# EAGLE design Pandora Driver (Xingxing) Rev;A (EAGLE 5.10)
MFG: AVX; PN: TCJR106M006R0500

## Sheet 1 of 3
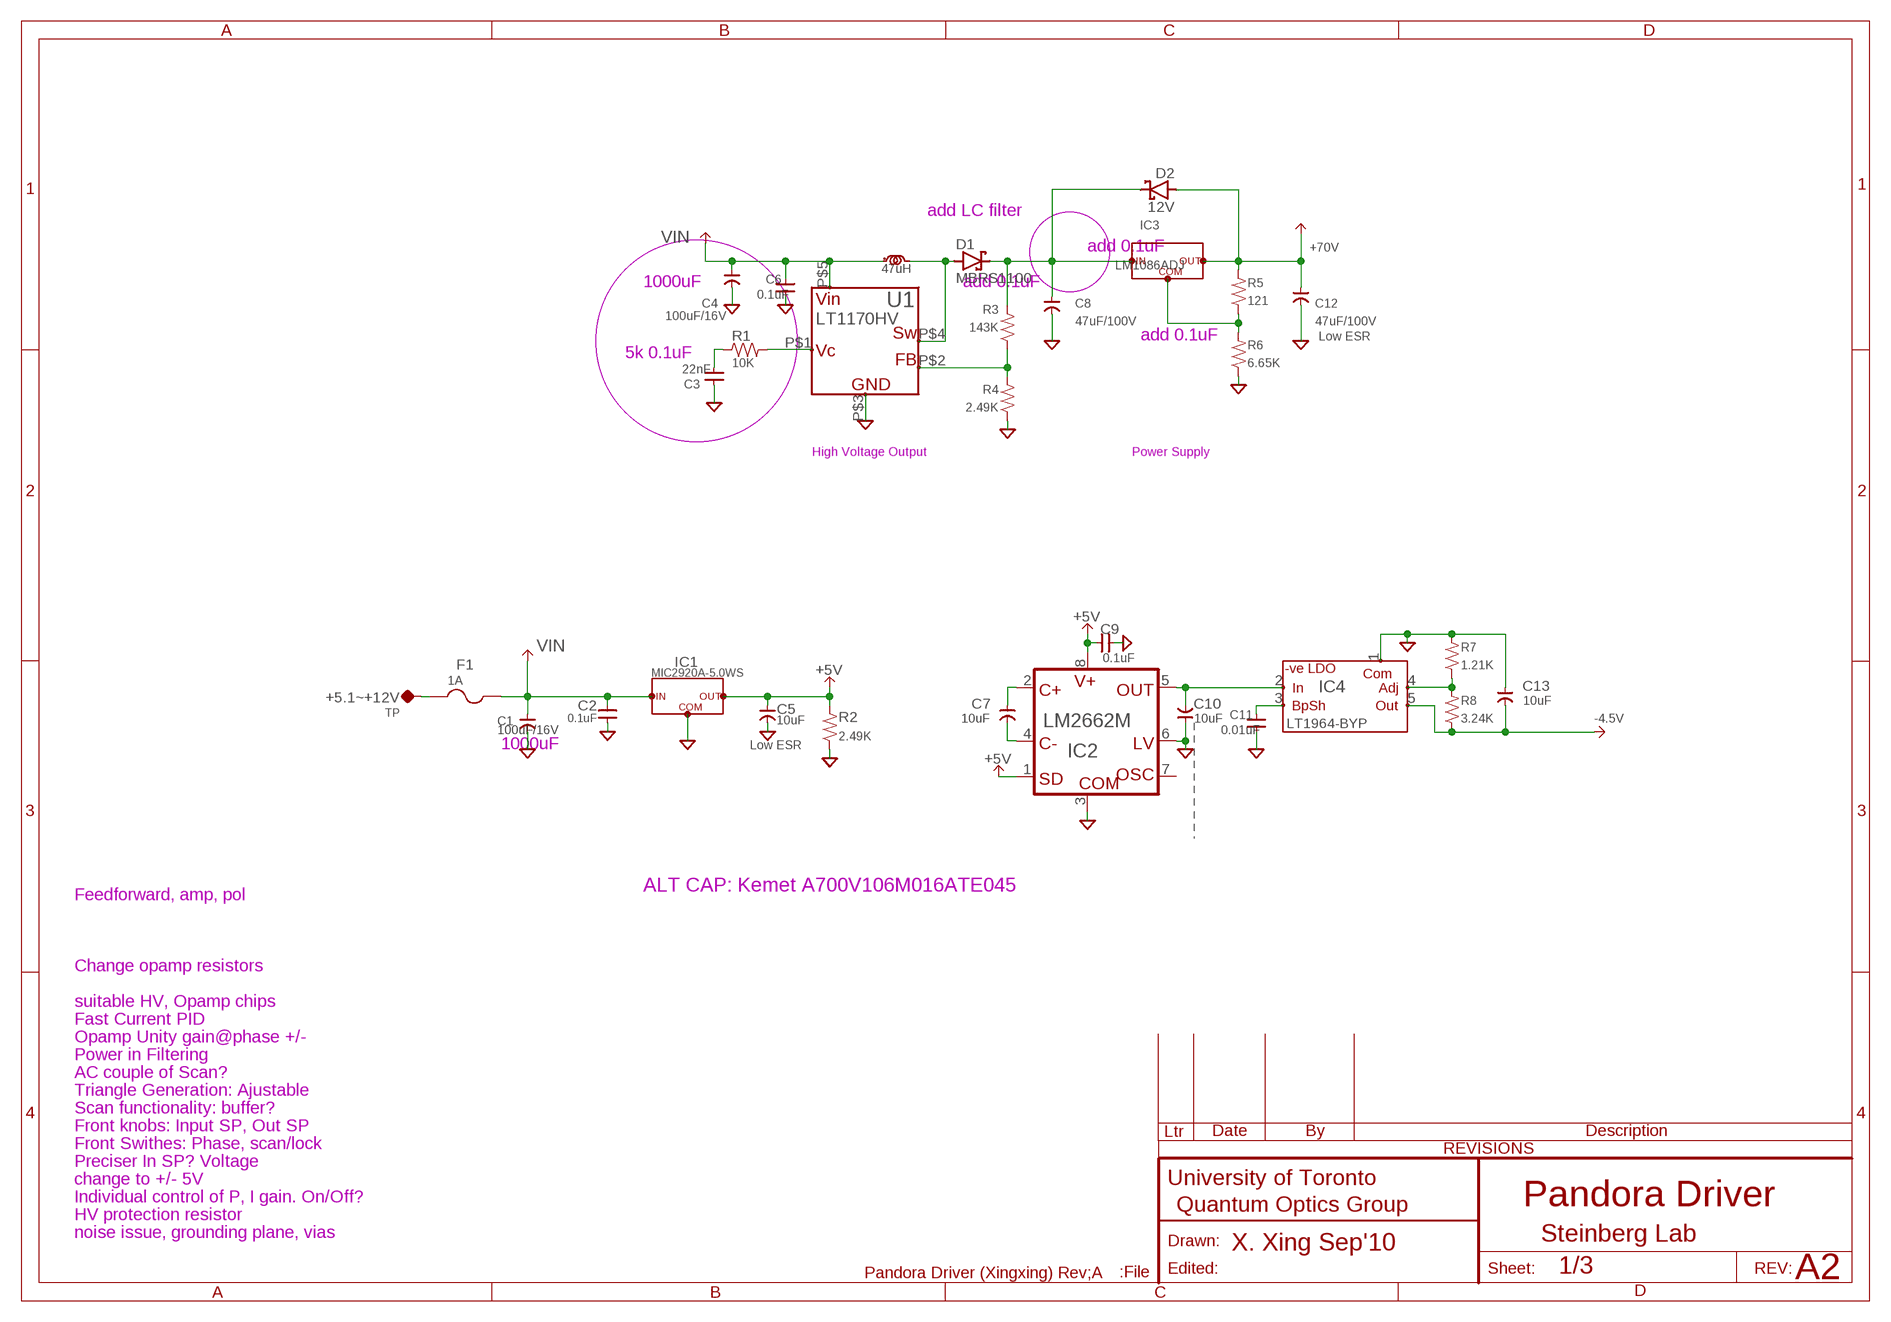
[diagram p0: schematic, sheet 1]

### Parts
+5.1~+12V  TP  TP-0.052"  [TP-0.052]
C1  100uF/16V  CAP-POL-PANA-D  [PANASONIC_D]
C2  0.1uF  CAP-V-0805  [2012(0805)]
C3  22nF  CAP-H-0805  [2012(0805)]
C4  100uF/16V  CAP-POL-PANA-D  [PANASONIC_D]
C5  10uF  CAP-POL--EIA7343  [7343]
C6  0.1uF  CAP-H-0805  [2012(0805)]
C7  10uF  CAP-POL--EIA7343  [7343]
C8  47uF/100V  CAP-POL-G13(X)  [PANASONIC_G13X]
C9  0.1uF  CAP-H-0805  [2012(0805)]
C10  10uF  CAP-POL--EIA7343  [7343]
C11  0.01uF  CAP-H-0805  [2012(0805)]
C12  47uF/100V  CAP-POL-G13(X)  [PANASONIC_G13X]
C13  10uF  CAP-POL--EIA7343  [7343]
D1  MBRS1100  MBRS130  [EIA-B(SMB)]
D2  12V  DIODE,SCHOTTKY-SOT-23  [SOT23]
F1  1A  FUSE-LITTLEFUSE_0154  [FUSE:LITTLEFUSE_0154]
IC1  MIC2920A-5.0WS  REGULATOR:3PIN-SOT223(TAB,2PINS)  [SOT223(C)]
IC2  LM2662M  LM2663M  [SOIC-8@1]
IC3  LM1086ADJ  REGULATOR:LM1086(LDO)-TO263  [TO263]
IC4  LT1964-BYP  REGULATOR:LT1964(NEG,200MA)-ES5-  [SOT23-5]
L1  47uH  INDUCTOR-PANASONIC_ELLATV  [PANASONIC_ELLATV(COIL)]
R1  10K  R-H-0805  [2012(0805)]
R2  2.49K  R-V-0805  [2012(0805)]
R3  143K  R-H-0805  [2012(0805)]
R4  2.49K  R-H-0805  [2012(0805)]
R5  121  R-H-0805  [2012(0805)]
R6  6.65K  R-H-0805  [2012(0805)]
R7  1.21K  R-H-0805  [2012(0805)]
R8  3.24K  R-H-0805  [2012(0805)]
U1  LT1170HV  [TO263-5]

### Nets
+5V [power]: C5.+VE(POS) C9.1 IC1.3(OUT) IC2.1(SD) IC2.8(V+) R2.2 ; also sheet 2,3
+70V [power]: C12.+(POS) D2.1(A) IC3.2(OUT) R5.2 ; also sheet 3
-4.5V [power]: C13.-VE(NEG) IC4.5(OUT) R8.1 ; also sheet 2,3
-5IN [power]: C10.-VE(NEG) IC2.5(OUT) IC4.2(IN)
GND: C1.-(NEG) C2.1 C3.2 C4.-(NEG) C5.-VE(NEG) C6.1 C8.-(NEG) C9.2 C10.+VE(POS) C11.1 C12.-(NEG) C13.+VE(POS) IC1.2(COM) IC2.3(COM) IC2.6(LV) IC4.1(COM) R2.1 R4.1 R6.1 R7.2 U1.P$3(GND) ; also sheet 2,3
N$010 [power]: +5.1~+12V.TP F1.1(1A)
N$13: R1.2 U1.P$1(VC)
N$17: C3.1 R1.1
N$19: R3.1 R4.2 U1.P$2(FB)
N$22 [power]: D1.A-(A) L1.2(B) U1.P$4(SW)
N$033 [power]: C8.+(POS) D1.K+(C) D2.3(C) IC3.3(VI) R3.2
N$034: IC3.1(COM) R5.1 R6.2
N$041: C7.+VE(POS) IC2.2(C+)
N$042: C7.-VE(NEG) IC2.4(C-)
N$057: C11.2 IC4.3(BP/SH)
N$060: IC4.4(ADJ) R7.1 R8.2
VIN [power]: C1.+(POS) C2.2 C4.+(POS) C6.2 F1.2(2A) IC1.1(VI) L1.1(A) U1.P$5(VIN)
Unconnected: IC2.7(OSC)

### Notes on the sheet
- add LC filter
- add 0.1uF
- 1000uF | add 0.1uF
- add 0.1uF | Low ESR
- 5k 0.1uF
- High Voltage Output | Power Supply
- 1000uF | Low ESR
- ALT CAP: Kemet A700V106M016ATE045
- Feedforward, amp, pol
- Change opamp resistors
- suitable HV, Opamp chips
- Fast Current PID
- Opamp Unity gain@phase +/-
- Power in Filtering
- AC couple of Scan?
- Triangle Generation: Ajustable
- Scan functionality: buffer?
- Front knobs: Input SP, Out SP
- Front Swithes: Phase, scan/lock
- Preciser In SP? Voltage
- change to +/- 5V
- Individual control of P, I gain. On/Off? | Pandora Driver
- HV protection resistor
- noise issue, grounding plane, vias | Steinberg Lab
- X. Xing Sep'10
- A2

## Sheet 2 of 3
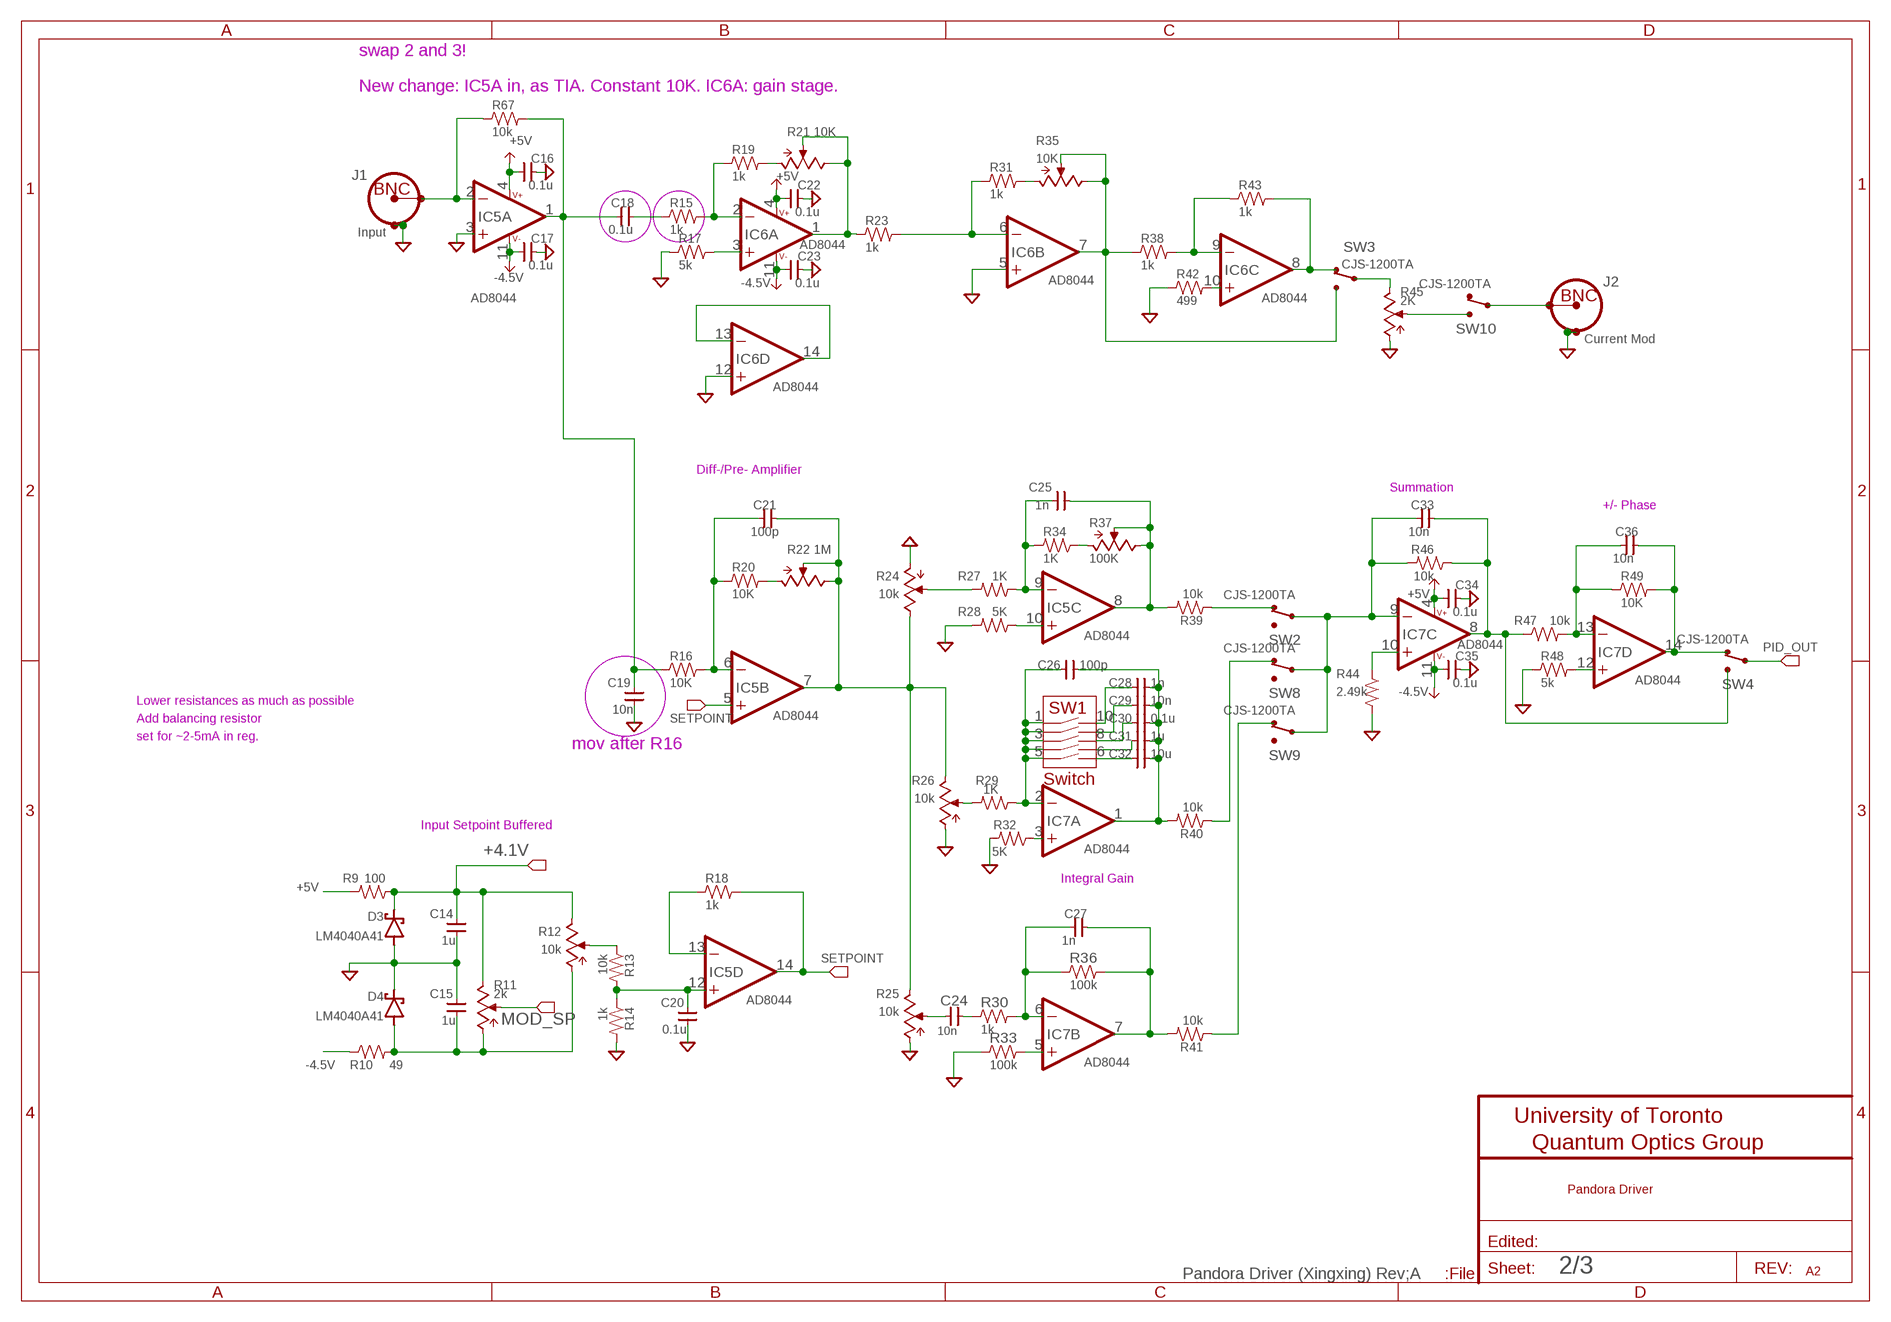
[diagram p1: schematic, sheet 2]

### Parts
C14  1u  CAP-H-0805  [2012(0805)]
C15  1u  CAP-H-0805  [2012(0805)]
C16  0.1u  CAP-H-0805  [2012(0805)]
C17  0.1u  CAP-H-0805  [2012(0805)]
C18  0.1u  CAP-H-0805  [2012(0805)]
C19  10n  CAP-H-0805  [2012(0805)]
C20  0.1u  CAP-H-0805  [2012(0805)]
C21  100p  CAP-H-0805  [2012(0805)]
C22  0.1u  CAP-H-0805  [2012(0805)]
C23  0.1u  CAP-H-0805  [2012(0805)]
C24  10n  CAP-H-0805  [2012(0805)]
C25  1n  CAP-H-0805  [2012(0805)]
C26  100p  CAP-H-0805  [2012(0805)]
C27  1n  CAP-H-0805  [2012(0805)]
C28  1n  CAP-H-0805  [2012(0805)]
C29  10n  CAP-H-0805  [2012(0805)]
C30  0.1u  CAP-H-0805  [2012(0805)]
C31  1u  CAP-H-0805  [2012(0805)]
C32  10u  CAP-H-0805  [2012(0805)]
C33  10n  CAP-H-0805  [2012(0805)]
C34  0.1u  CAP-H-0805  [2012(0805)]
C35  0.1u  CAP-H-0805  [2012(0805)]
C36  10n  CAP-H-0805  [2012(0805)]
D3  LM4040A41  DIODE,SCHOTTKY-SOT-23  [SOT23]
D4  LM4040A41  DIODE,SCHOTTKY-SOT-23  [SOT23]
IC5  AD8044  OPAMP:LT1491(RRIO+,QUAD)-SO14  [SOIC-14]
IC6  AD8044  OPAMP:LT1491(RRIO+,QUAD)-SO14  [SOIC-14]
IC7  AD8044  OPAMP:LT1491(RRIO+,QUAD)-SO14  [SOIC-14]
J1  Input  CONN-BNC-TYPE1VERT  [CONN-BNC-AMP-TYPE1VERT]
J2  Current Mod  CONN-BNC-TYPE1VERT  [CONN-BNC-AMP-TYPE1VERT]
R9  100  R-H-0805  [2012(0805)]
R10  49  R-H-0805  [2012(0805)]
R11  2k  POT-3214W_TRIM  [BOURNS_3214]
R12  10k  POT-3214W_TRIM  [BOURNS_3214]
R13  10k  R-H-0805  [2012(0805)]
R14  1k  R-H-0805  [2012(0805)]
R15  1k  R-H-0805  [2012(0805)]
R16  10K  R-H-0805  [2012(0805)]
R17  5k  R-H-0805  [2012(0805)]
R18  1k  R-H-0805  [2012(0805)]
R19  1k  R-H-0805  [2012(0805)]
R20  10K  R-H-0805  [2012(0805)]
R21  10K  POT-3214W_TRIM  [BOURNS_3214]
R22  1M  POT-3214W_TRIM  [BOURNS_3214]
R23  1k  R-H-0805  [2012(0805)]
R24  10k  POT-3214W_TRIM  [BOURNS_3214]
R25  10k  POT-3214W_TRIM  [BOURNS_3214]
R26  10k  POT-3214W_TRIM  [BOURNS_3214]
R27  1K  R-H-0805  [2012(0805)]
R28  5K  R-H-0805  [2012(0805)]
R29  1K  R-H-0805  [2012(0805)]
R30  1k  R-H-0805  [2012(0805)]
R31  1k  R-H-0805  [2012(0805)]
R32  5K  R-H-0805  [2012(0805)]
R33  100k  R-H-0805  [2012(0805)]
R34  1K  R-H-0805  [2012(0805)]
R35  10K  POT-3214W_TRIM  [BOURNS_3214]
R36  100k  R-H-0805  [2012(0805)]
R37  100K  POT-3214W_TRIM  [BOURNS_3214]
R38  1k  R-H-0805  [2012(0805)]
R39  10k  R-H-0805  [2012(0805)]
R40  10k  R-H-0805  [2012(0805)]
R41  10k  R-H-0805  [2012(0805)]
R42  499  R-H-0805  [2012(0805)]
R43  1k  R-H-0805  [2012(0805)]
R44  2.49k  R-H-0805  [2012(0805)]
R45  2K  POT-3214W_TRIM  [BOURNS_3214]
R46  10k  R-H-0805  [2012(0805)]
R47  10k  R-H-0805  [2012(0805)]
R48  5k  R-H-0805  [2012(0805)]
R49  10K  R-H-0805  [2012(0805)]
R67  10k  R-H-0805  [2012(0805)]
SW1  Switch  SWITCH:5PDT  [SWITCH:CTS219-5MST]
SW2  CJS-1200TA  SWITCH:SPDT_CJS-1200A1  [SWITCH:DIP(COPAL)]
SW3  CJS-1200TA  SWITCH:SPDT_CJS-1200A1  [SWITCH:DIP(COPAL)]
SW4  CJS-1200TA  SWITCH:SPDT_CJS-1200A1  [SWITCH:DIP(COPAL)]
SW8  CJS-1200TA  SWITCH:SPDT_CJS-1200A1  [SWITCH:DIP(COPAL)]
SW9  CJS-1200TA  SWITCH:SPDT_CJS-1200A1  [SWITCH:DIP(COPAL)]
SW10  CJS-1200TA  SWITCH:SPDT_CJS-1200A1  [SWITCH:DIP(COPAL)]

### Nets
+4.1V: C14.2 D3.3(C) R9.1 R11.CW R12.CW ; also sheet 3
+5V [power]: C16.1 C22.1 C34.1 IC5.4(V++) IC6.4(V++) IC7.4(V++) R9.2 ; also sheet 1,3
-4.5V [power]: C17.1 C23.1 C35.1 IC5.11(V-) IC6.11(V-) IC7.11(V-) R10.1 ; also sheet 1,3
CUR_MOD2: J2.CONDUCTOR SW10.COM
CUR_MOD_P3: IC6.7(B:OUT) R35.CW R35.W R38.1 SW3.1(NO\UP\RIGHT)
CUR_MOD_P4: IC6.8(C:OUT) R43.2 SW3.2(NC\DOWN\LEFT)
GND: C14.1 C15.2 C16.2 C17.2 C19.1 C20.1 C22.2 C23.2 C34.2 C35.2 D3.1(A) D4.3(C) IC5.3(A:+IN) IC6.12(D:+IN) J1.SHIELD1 J1.SHIELD2 J2.SHIELD1 J2.SHIELD2 R14.2 R17.1 R24.CCW R25.CCW R26.CCW R28.2 R32.2 R33.1 R42.1 R44.2 R45.CCW R48.1 ; also sheet 1,3
INPUT_BUF: C18.2 C19.2 IC5.1(A:OUT) R16.1 R67.2
MOD_SP: R11.W
N$004: C21.1 IC5.6(B:-IN) R16.2 R20.1
N$006: C31.1 SW1.7(4B)
N$009: C21.2 IC5.7(B:OUT) R22.CW R22.W R24.CW R25.CW R26.CW
N$011: IC6.3(A:+IN) R17.2
N$012: R24.W R27.2
N$014: C25.1 IC5.9(C:-IN) R27.1 R34.2
N$015: C25.2 IC5.8(C:OUT) R37.CW R37.W R39.2
N$016: C29.1 SW1.9(2B)
N$018: C30.1 SW1.8(3B)
N$020: C32.1 SW1.6(5B)
N$021: C26.2 C28.2 C29.2 C30.2 C31.2 C32.2 IC7.1(A:OUT) R40.2
N$023: R26.W R29.2
N$024: C20.2 IC5.12(D:+IN) R13.2 R14.1
N$025: R12.W R13.1
N$026: C26.1 IC7.2(A:-IN) R29.1 SW1.1(1A) SW1.2(2A) SW1.3(3A) SW1.4(4A) SW1.5(5A)
N$027: C28.1 SW1.10(1B)
N$028: R45.W SW10.1(NO\UP\RIGHT)
N$029: C33.2 IC7.8(C:OUT) R46.1 R47.1 SW4.1(NO\UP\RIGHT)
N$030: IC7.5(B:+IN) R33.2
N$031: IC5.13(D:-IN) R18.1
N$032: IC5.10(C:+IN) R28.1
N$035: IC7.10(C:+IN) R44.1
N$037: IC7.12(D:+IN) R48.2
N$038: C36.2 IC7.14(D:OUT) R49.2 SW4.2(NC\DOWN\LEFT)
N$039: R20.2 R22.CCW
N$040: C24.1 R25.W
N$050: C27.1 IC7.6(B:-IN) R30.2 R36.1
N$051: C27.2 IC7.7(B:OUT) R36.2 R41.2
N$052: C24.2 R30.1
N$053: C36.1 IC7.13(D:-IN) R47.2 R49.1
N$054: IC6.10(C:+IN) R42.2
N$056: IC7.3(A:+IN) R32.1
N$061: C33.1 IC7.9(C:-IN) R46.2 SW2.COM SW8.COM SW9.COM
N$062: IC6.13(D:-IN) IC6.14(D:OUT)
N$063: IC6.1(A:OUT) R21.CW R21.W R23.1
N$085: R34.1 R37.CCW
N$091: IC5.2(A:-IN) J1.CONDUCTOR R67.1
N$093: C15.1 D4.1(A) R10.2 R11.CCW R12.CCW
N$097: C18.1 R15.1
N$098: IC6.2(A:-IN) R15.2 R19.1
N$100: IC6.6(B:-IN) R23.2 R31.1
N$101: IC6.9(C:-IN) R38.2 R43.1
N$102: R40.1 SW8.2(NC\DOWN\LEFT)
N$103: R41.1 SW9.2(NC\DOWN\LEFT)
N$104: R39.1 SW2.2(NC\DOWN\LEFT)
N$105: R19.2 R21.CCW
N$106: R31.2 R35.CCW
N$107: R45.CW SW3.COM
PID_OUT: SW4.COM ; also sheet 3
SETPOINT: IC5.5(B:+IN) IC5.14(D:OUT) R18.2 ; also sheet 3
Unconnected: IC6.5(B:+IN) SW2.1(NO\UP\RIGHT) SW8.1(NO\UP\RIGHT) SW9.1(NO\UP\RIGHT) SW10.2(NC\DOWN\LEFT)

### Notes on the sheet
- swap 2 and 3!
- New change: IC5A in, as TIA. Constant 10K. IC6A: gain stage.
- Diff-/Pre- Amplifier
- Summation
- +/- Phase
- Lower resistances as much as possible
- Add balancing resistor
- set for ~2-5mA in reg.
- mov after R16
- Input Setpoint Buffered
- Integral Gain
- Pandora Driver
- A2

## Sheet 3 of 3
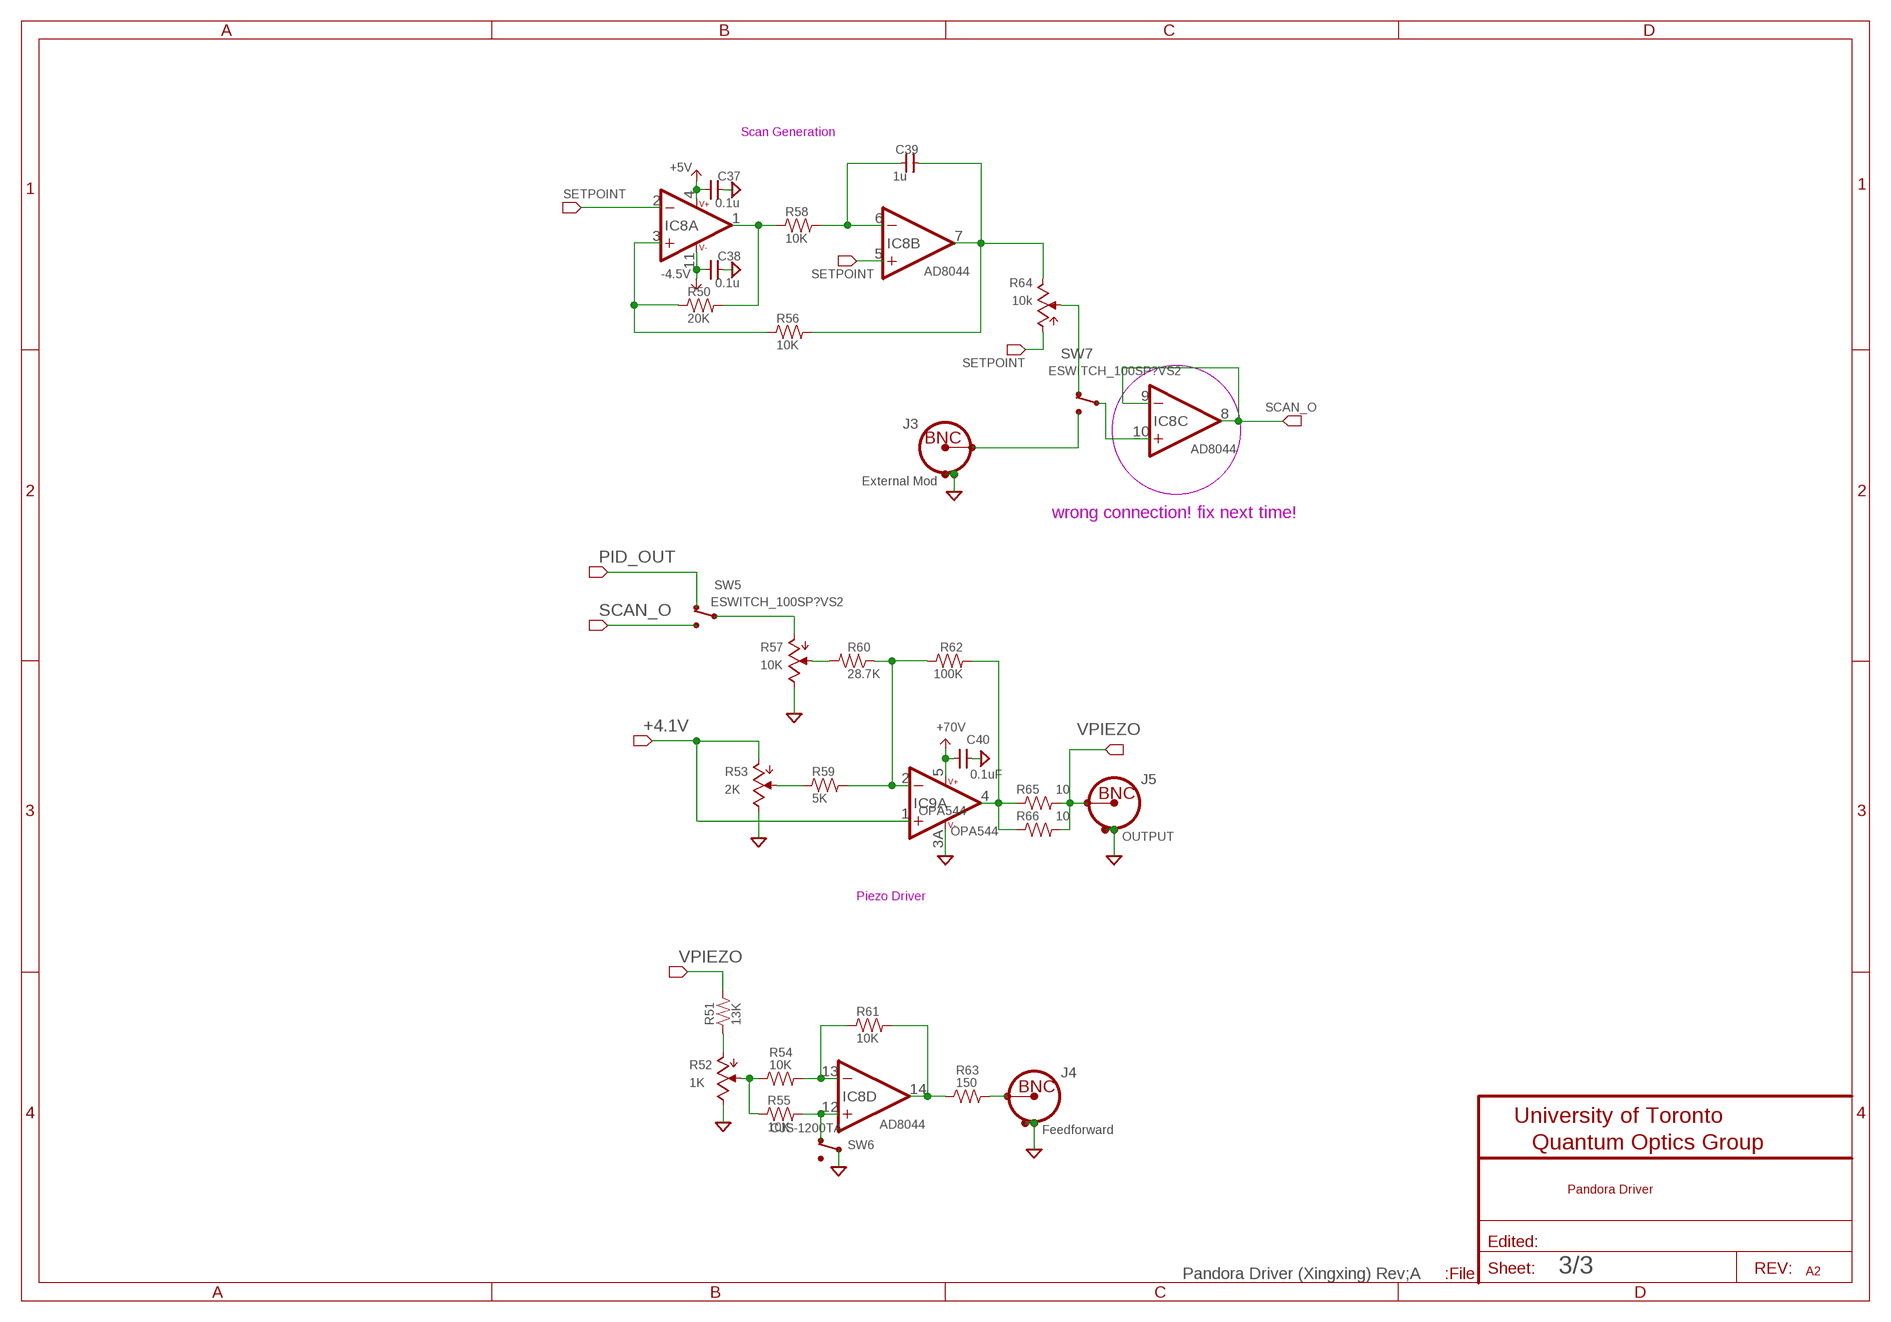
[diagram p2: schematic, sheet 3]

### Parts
C37  0.1u  CAP-H-0805  [2012(0805)]
C38  0.1u  CAP-H-0805  [2012(0805)]
C39  1u  CAP-H-0805  [2012(0805)]
C40  0.1uF  CAP-H-0805  [2012(0805)]
IC8  AD8044  OPAMP:LT1491(RRIO+,QUAD)-SO14  [SOIC-14]
IC9  OPA544  OPAMP:OPA544-TO263(KTT)  [TO263-5(KTT)]
J3  External Mod  CONN-BNC-TYPE1VERT  [CONN-BNC-AMP-TYPE1VERT]
J4  Feedforward  CONN-BNC-TYPE1VERT  [CONN-BNC-AMP-TYPE1VERT]
J5  OUTPUT  CONN-BNC-TYPE1VERT  [CONN-BNC-AMP-TYPE1VERT]
R50  20K  R-H-0805  [2012(0805)]
R51  13K  R-H-0805  [2012(0805)]
R52  1K  POT-3214W_TRIM  [BOURNS_3214]
R53  2K  POT-3590  [BOURNS_3590]
R54  10K  R-H-0805  [2012(0805)]
R55  10K  R-H-0805  [2012(0805)]
R56  10K  R-H-0805  [2012(0805)]
R57  10K  POT-3214W_TRIM  [BOURNS_3214]
R58  10K  R-H-0805  [2012(0805)]
R59  5K  R-H-0805  [2012(0805)]
R60  28.7K  R-H-0805  [2012(0805)]
R61  10K  R-H-0805  [2012(0805)]
R62  100K  R-H-0805  [2012(0805)]
R63  150  R-H-0805  [2012(0805)]
R64  10k  POT-3214W_TRIM  [BOURNS_3214]
R65  10  R-H-0805  [2012(0805)]
R66  10  R-H-0805  [2012(0805)]
SW5  ESWITCH_100SP?VS2  SWITCH:SPDT-ESWITCH_100SP?VS2  [SWITCH-ESWITCH_100SP?VS2]
SW6  CJS-1200TA  SWITCH:SPDT_CJS-1200A1  [SWITCH:DIP(COPAL)]
SW7  ESWITCH_100SP?VS2  SWITCH:SPDT-ESWITCH_100SP?VS2  [SWITCH-ESWITCH_100SP?VS2]

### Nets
+4.1V: IC9.1(A:+IN) R53.CCW ; also sheet 2
+5V [power]: C37.1 IC8.4(V++) ; also sheet 1,2
+70V [power]: C40.1 IC9.5(B:V++) ; also sheet 1
-4.5V [power]: C38.1 IC8.11(V-) ; also sheet 1,2
GND: C37.2 C38.2 C40.2 IC9.3A(B:V-) J3.SHIELD1 J3.SHIELD2 J4.SHIELD1 J4.SHIELD2 J5.SHIELD1 J5.SHIELD2 R52.CW R53.CW R57.CW SW6.COM ; also sheet 1,2
N$001: R51.1 R52.CCW
N$002: R52.W R54.1 R55.1
N$003: IC8.13(D:-IN) R54.2 R61.1
N$005: IC8.14(D:OUT) R61.2 R63.1
N$007: IC8.12(D:+IN) R55.2 SW6.2(NC\DOWN\LEFT)
N$008: J4.CONDUCTOR R63.2
N$036: IC8.3(A:+IN) R50.1 R56.1
N$043: C39.2 IC8.7(B:OUT) R56.2 R64.CW
N$044: IC8.1(A:OUT) R50.2 R58.1
N$045: C39.1 IC8.6(B:-IN) R58.2
N$046: IC9.2(A:-IN) R59.2 R60.1 R62.1
N$047: IC9.4(A:OUT) R62.2 R65.1 R66.1
N$048: R53.W R59.1
N$049: R57.W R60.2
N$055: R64.W SW7.NC(NC\DOWN\LEFT)
N$058: IC8.10(C:+IN) SW7.C(COM)
N$059: J3.CONDUCTOR SW7.NO(NO\UP\RIGHT)
PID_OUT: SW5.NC(NC\DOWN\LEFT) ; also sheet 2
PIEZO_CTRL1: R57.CCW SW5.C(COM)
SCAN_O: IC8.8(C:OUT) IC8.9(C:-IN) SW5.NO(NO\UP\RIGHT)
SETPOINT: IC8.2(A:-IN) IC8.5(B:+IN) R64.CCW ; also sheet 2
VPIEZO: J5.CONDUCTOR R51.2 R65.2 R66.2
Unconnected: SW6.1(NO\UP\RIGHT)

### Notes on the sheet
- Scan Generation
- wrong connection! fix next time!
- Piezo Driver
- Pandora Driver
- A2

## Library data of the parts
+5.1~+12V = QuantumOptics:TP: Testpoint, either SMT pad, small hole or loop style TP such as Keystone 5002K (0.042").
C1 C4 C8 C12 = QuantumOptics-x:CAP-POL-: Capacitor, Polarized, SMT 0805 and up, probably tantalum.
C2 = QuantumOptics:CAP-V-: Cap, SMT and Through-hole, 0402 and up.
C3 C6 C9 C11 C14-C40 = QuantumOptics:CAP-H-: Cap, SMT and Through-hole, 0402 and up.
C5 C7 C10 C13 = QuantumOptics:CAP-POL-: Capacitor, Polarized, SMT 0805 and up, probably tantalum.
D1 = QuantumOptics:MBRS130: MBRS130LT3, ON Semi et al, schottky, 1A 30V, SMB. General purpose schottky in SMT.
D2-D4 = QuantumOptics:DIODE,SCHOTTKY: Schottky Diode, general purpose.
F1 = QuantumOptics:FUSE: Fuse
IC1 = QuantumOptics-x:REGULATOR:3PIN: LM1086-xxx, National Semiconductor, LDO, adjustable or fixed. http://cache.national.com/ds/LM/LM1086.pdf
IC2 = QuantumOptics:LM2663: LM2663, switched cap DC-DC converter. Inverter, doubler, supply splitter.
IC3 = QuantumOptics:REGULATOR:LM1086(LDO): LM1086-xxx, National Semiconductor, LDO, adjustable or fixed. http://cache.national.com/ds/LM/LM1086.pdf
IC4 = QuantumOptics:REGULATOR:LT1964(NEG,200MA): LT1964, LinTech, negative LDO, 200mA, fixed or -5V, very low noise. Three versions: 1) adj with shutdown, 2) adj with reference bypass, 3) fixed 5V with bypass and shutdown. http://www.linear.com/pc/downloadDocument.do?navId=H0,C1,C1003,C1040,C1019,P2168,D1258
IC5-IC8 = QuantumOptics:OPAMP:LT1491(RRIO+,QUAD): LT1491, Linear Technology quad op-amp. Low power, RRIO plus "over the top" inputs, high gain, low Vio, low Ib, low GBW too.
IC9 = QuantumOptics:OPAMP:OPA544: Op Amp, generic, pick the right package. e.g. AD8605: SOT-23-5, RRIO, 10MHz, Ib = 1pA, Vio < 65uV, 2.7-5.5V.
J1-J5 = QuantumOptics:CONN-BNC: BNC PCB, horizontal or vertical, e.g. Horiz: Amp (5)227677-1, nut 1-329631-2, shoulder washer 330620, vert isolated 5227222-6, http://catalog.tycoelectronics.com/TE/bin/TE.Connect?C=1&M=BYPN&TCPN=5227222-6&RQPN=5227222-6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; DESC: Input?
L1 = QuantumOptics-x:INDUCTOR: Inductor, generic inductor.
R1 R3-R10 R13-R20 R23 R27-R34 R36 R38-R44 R46-R51 R54-R56 R58-R63 R65-R67 = QuantumOptics:R-H-*: Resistor, SMT & Through-Hole, horizontal symbol
R2 = QuantumOptics:R-V-*: Resistor, SMT & Through-Hole, vertical symbol
R11 R12 R21 R22 R24-R26 R35 R37 R45 R53 = QuantumOptics:POT: Pot, regular or trimpot
R52 R57 R64 = QuantumOptics-x:POT: Pot, regular or trimpot
SW1 = QuantumOptics-x:SWITCH:5PDT: 5 position DIP switch, through-hole.
SW2-SW10 = QuantumOptics:SWITCH:SPDT: Switch, SPDT
U1 = QuantumOptics:LT1170HV

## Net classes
0 default: width 0.178 mm, drill 0.508 mm, clearance 0.178 mm
1 power: width 0.508 mm, drill 0.711 mm

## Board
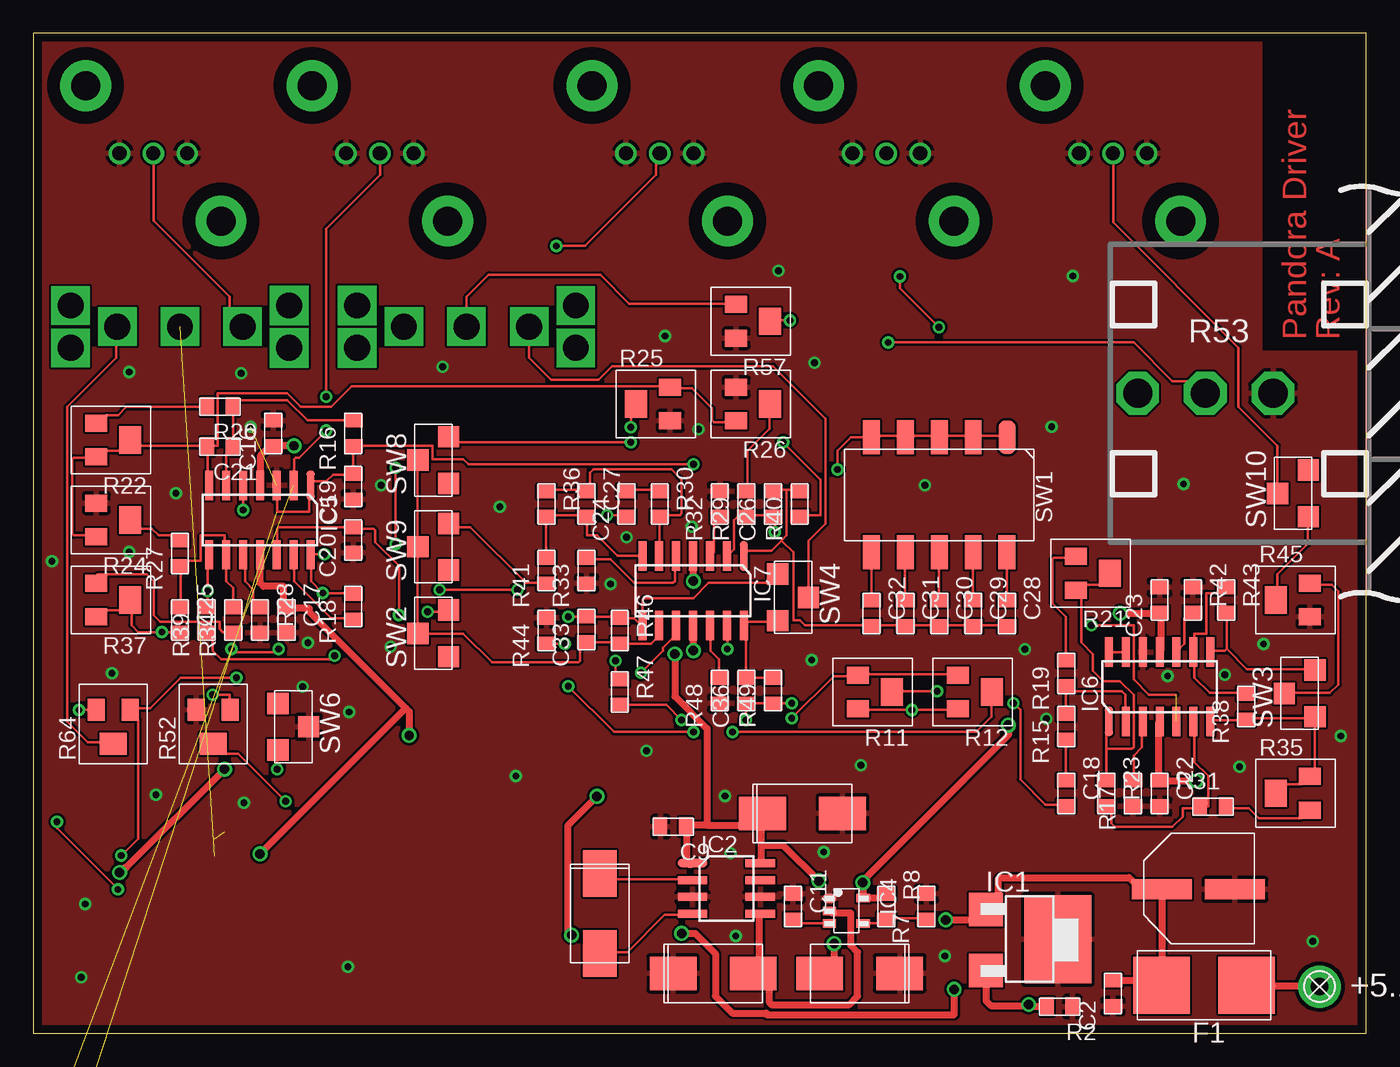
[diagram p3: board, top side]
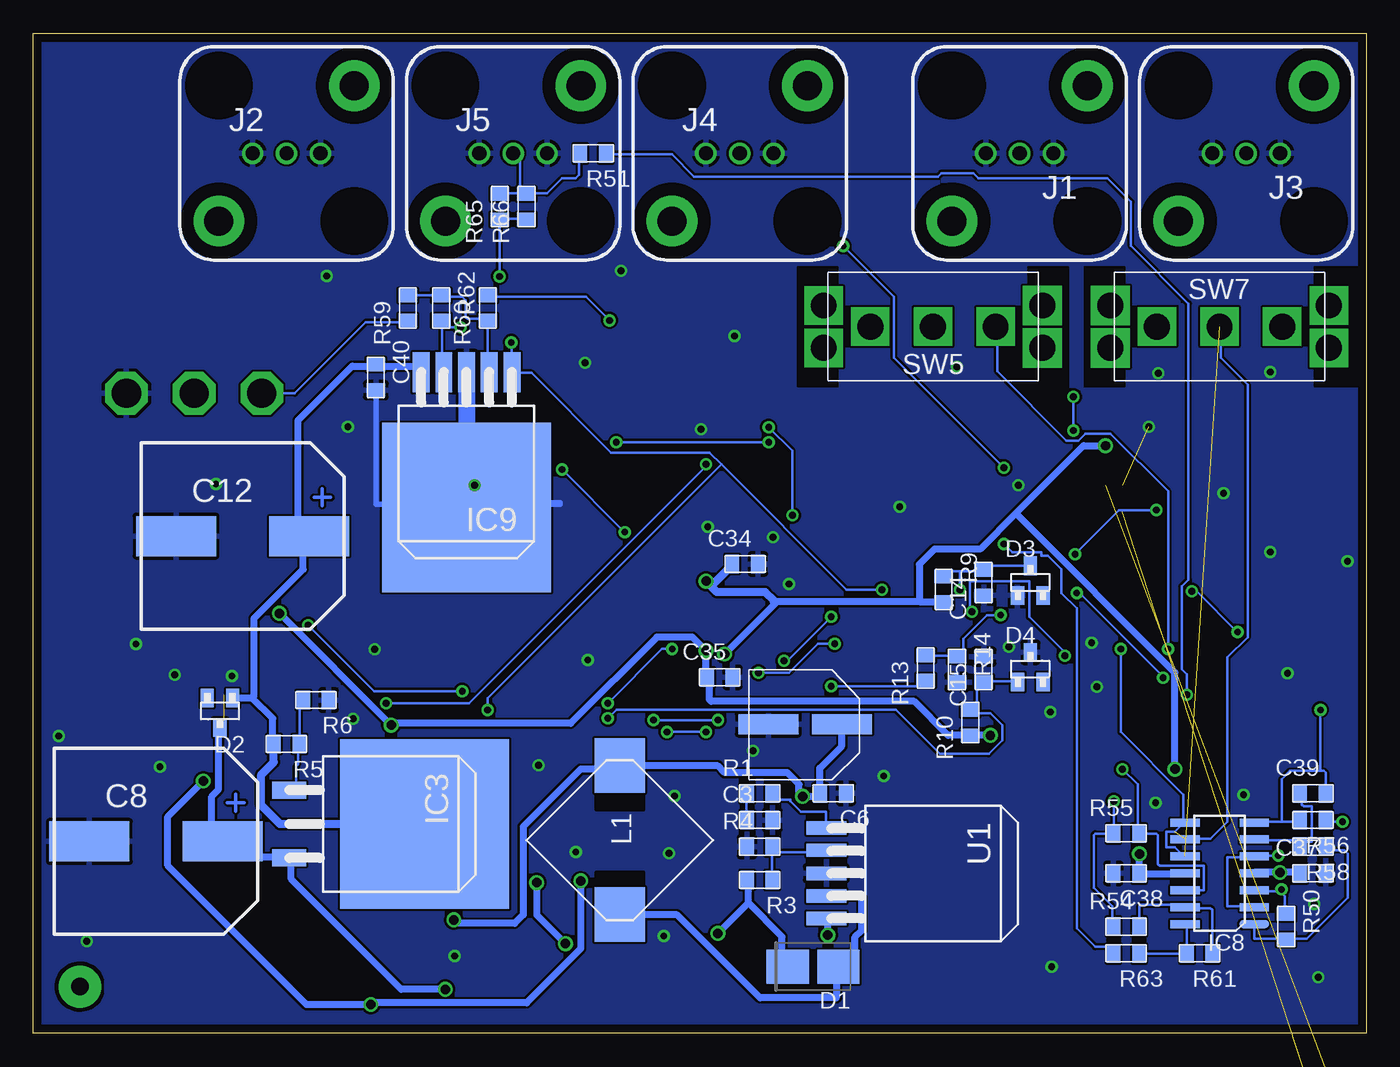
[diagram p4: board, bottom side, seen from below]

Size 100 x 75 mm. Coordinates in mm from the lower left corner, seen from the top.
Outline: 0,0 100,0 100,75 0,75 0,0
Copper layers (1+16): Top 0.035mm / dielectric 1.5mm / Bottom 0.035mm
Design rules "DRC standard check": minimum track width 7mil, minimum drill 20mil, track to track 7mil, track to pad 7mil, pad to pad 7mil, via to via 7mil, smd to smd 0mil, copper to edge 25mil, drill to drill 8mil, minimum pad ring 10mil, minimum via ring 8mil, stop-mask expansion 4mil, vias tented up to drill 0mil, thermal gap 10mil
bKeepout: area 25,6 to 34,18

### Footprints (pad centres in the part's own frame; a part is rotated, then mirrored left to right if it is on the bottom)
TP-0.052 = drill 1.321 pad 3.175 round: TP 0,0
PANASONIC_D = smd 4.5 x 1.5: + 2.75,0; - -2.75,0
2012(0805) = smd 1.016 x 1.397: 1 -0.953,0; 2 0.953,0
7343 = smd 3.5 x 2.5: +VE -3,0; -VE 3,0
PANASONIC_G13X = smd 3 x 6: + 0,-5; - 0,5
EIA-B(SMB) = smd 3.175 x 2.54: A- -1.905,0; K+ 1.905,0
SOT23 = smd 1 x 1.4: 1 -0.953,-0.953; 2 0.953,-0.953; 3 0,1.27
FUSE:LITTLEFUSE_0154 = smd 4.25 x 4.25: 1 -3.185,0; 2 3.185,0
SOT223(C) = smd 2.54 x 2.54: 1 -2.286,-2.54; 3 2.286,-2.54 | smd 6.6 x 5: 2 -0.05,2.87
SOIC-8@1 = smd 0.6 x 2.2: 1 -1.27,-2.54; 2 0,-2.54; 3 1.27,-2.54; 4 2.54,-2.54; 5 2.54,2.54; 6 1.27,2.54; 7 0,2.54; 8 -1.27,2.54
TO263 = smd 1.27 x 2.54: 1 -2.54,0; 3 2.54,0 | smd 12.7 x 12.7: 2 0,10.16
SOT23-5 = smd 0.635 x 0.991: 1 -0.635,-1.27; 2 0.318,-1.27; 3 1.27,-1.27; 4 1.27,1.27; 5 -0.635,1.27
SOIC-14 = smd 0.6 x 2.2: 1 -3.81,-2.6; 2 -2.54,-2.6; 3 -1.27,-2.6; 4 0,-2.6; 5 1.27,-2.6; 6 2.54,-2.6; 7 3.81,-2.6; 8 3.81,2.6; 9 2.54,2.6; 10 1.27,2.6; 11 0,2.6; 12 -1.27,2.6; 13 -2.54,2.6; 14 -3.81,2.6
TO263-5(KTT) = smd 1.27 x 3: 1 -3.404,0; 2 -1.702,0; 3A 0,0; 4 1.702,0; 5 3.404,0 | smd 12.7 x 12.7: 3B 0,10.16
CONN-BNC-AMP-TYPE1VERT = drill 1.067 round: CONDUCTOR 0,0; SHIELD1 -2.54,0; SHIELD2 2.54,0 | drill 2.184 pad 3.81 round: MTG1 -5.08,-5.08; MTG2 5.08,5.08
PANASONIC_ELLATV(COIL) = smd 4.064 x 3.81: 1 -5.588,0; 2 5.588,0
BOURNS_3214 = smd 1.651 x 1.27: CCW 1.27,-1.27; CW 1.27,1.27 | smd 1.651 x 2.032: W -1.27,0
BOURNS_3590 = drill 2.184 octagon: CCW -12.065,0; CW -6.985,0; W -17.145,0
SWITCH:CTS219-5MST = smd 1.27 x 2.54: 1 -5.08,-4.318; 2 -2.54,-4.318; 3 0,-4.318; 4 2.54,-4.318; 5 5.08,-4.318; 6 5.08,4.318; 7 2.54,4.318; 8 0,4.318; 9 -2.54,4.318; 10 -5.08,4.318
SWITCH:DIP(COPAL) = smd 1.6 x 1.6: 1 -1.75,-1.15; 2 1.75,-1.15; COM 0,1.15
SWITCH-ESWITCH_100SP?VS2 = drill 1.93 square: C 0,0; MTG3 8.2,1.59; MTG4 8.2,-1.59; NC 4.7,0; NO -4.7,0 | drill 1.93 pad 2.946 square: MTG1 -8.2,-1.59; MTG2 -8.2,1.59
TO263-5 = smd 1 x 3: P$1 -3.404,-8.001; P$2 -1.727,-8.001; P$3 0,-8.001; P$4 1.702,-8.001; P$5 3.378,-7.976

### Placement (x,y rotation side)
+5.1~+12V  96.5,3.5 0 top
C1  87.4,10.8 180 top
C2  81,3 90 top
C3  45.5,16 0 bottom
C4  42.1,23.2 0 bottom
C5  57.7,16.5 0 top
C6  40,18 180 bottom
C7  42.5,9 270 top
C8  90.8,14.4 90 bottom
C9  48,15.5 180 top
C10  51,4.5 0 top
C11  57,9.5 270 top
C12  84.3,37.3 90 bottom
C13  62,4.5 180 top
C14  28.7,33.8 90 bottom
C15  28.7,27.3 90 bottom
C16  18,45 90 top
C17  19,31 270 top
C18  77.5,18 270 top
C19  24,41 90 top
C20  24,37 90 top
C21  14,44 180 top
C22  84.5,18 270 top
C23  84.5,32.5 90 top
C24  44.5,39.7 90 top
C25  11,31 270 top
C26  55.5,39.7 90 top
C27  41.5,39.7 270 top
C28  73.05,31.5 270 top
C29  70.51,31.5 270 top
C30  67.97,31.5 270 top
C31  65.43,31.5 270 top
C32  62.89,31.5 270 top
C33  41.5,30.3 90 top
C34  46.6,35.2 0 bottom
C35  48.5,26.7 0 bottom
C36  53.5,25.7 90 top
C37  4,12 0 bottom
C38  18,12 180 bottom
C39  4,18 0 bottom
C40  74.3,49.2 270 bottom
D1  41.5,5 180 bottom
D2  86,24.2 180 bottom
D3  25.2,33.8 0 bottom
D4  25.2,27.3 0 bottom
F1  87.83,3.61 180 top
IC1  74,7 270 top
IC2  52,11.5 270 top
IC3  80.8,15.7 270 bottom
IC4  61,9.5 270 top
IC5  17,38.5 180 top
IC6  84.5,26 0 top
IC7  49.5,33.2 180 top
IC8  11,12 90 bottom
IC9  67.5,49.6 180 bottom
J1  26,66 180 bottom
J2  81,66 0 bottom
J3  9,66 180 bottom
J4  47,66 0 bottom
J5  64,66 0 bottom
L1  56,14.5 270 bottom
R1  45.5,18 0 bottom
R2  77,2 180 top
R3  45.5,11.5 180 bottom
R4  45.5,14 0 bottom
R5  81,21.7 180 bottom
R6  78.8,25 180 bottom
R7  67,9.5 90 top
R8  64,9.5 270 top
R9  31.7,33.3 270 bottom
R10  29.7,23.3 90 bottom
R11  63.15,25.6 180 top
R12  70.65,25.6 180 top
R13  33.05,27.4 90 bottom
R14  30.7,27.3 270 bottom
R15  77.5,23 90 top
R16  24,45 90 top
R17  82.5,18 90 top
R18  24,32 90 top
R19  77.5,27 90 top
R20  14,47 180 top
R21  79.5,34.5 180 top
R22  6,44.5 180 top
R23  80.5,18 270 top
R24  6,38.5 180 top
R25  46.5,47.2 0 top
R26  54,47.2 180 top
R27  11,36 90 top
R28  17,31 270 top
R29  53.5,39.7 90 top
R30  47,39.7 270 top
R31  88.5,17 0 top
R32  51.5,39.7 90 top
R33  41.5,34.7 90 top
R34  15,31 90 top
R35  94.5,18 0 top
R36  38.5,39.7 270 top
R37  6,32.5 180 top
R38  91,24.5 90 top
R39  13,31 90 top
R40  57.5,39.7 90 top
R41  38.5,34.7 90 top
R42  87,32.5 270 top
R43  89.5,32.5 270 top
R44  38.5,30.2 90 top
R45  94.5,32.5 0 top
R46  44,30.2 270 top
R47  44,25.6 270 top
R48  51.5,25.7 90 top
R49  55.5,25.7 90 top
R50  6,8 270 bottom
R51  58,66 180 bottom
R52  13.5,23 90 top
R53  100,48 0 top
R54  18,8 0 bottom
R55  18,15 0 bottom
R56  4,16 180 bottom
R57  54,53.4 180 top
R58  4,14 180 bottom
R59  71.9,54.4 90 bottom
R60  65.9,54.4 90 bottom
R61  12.5,6 180 bottom
R62  69.4,54.4 270 bottom
R63  18,6 180 bottom
R64  6,23 90 top
R65  65,62 90 bottom
R66  63,62 90 bottom
R67  not placed on the board
SW1  67.97,40.39 180 top
SW2  30,30 90 top
SW3  95,25.5 90 top
SW4  57,32.7 270 top
SW5  32.5,53 180 bottom
SW6  19.5,23 270 top
SW7  11,53 0 bottom
SW8  30,43 90 top
SW9  30,36.5 90 top
SW10  94.5,40.5 90 top
U1  32.5,12 270 bottom

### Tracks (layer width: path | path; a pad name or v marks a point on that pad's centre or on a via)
+4.1V  (via drill 0.51)
  Top 0.178: R11.CW 61.98,24.26 v65.91,24.26 69.34,24.26 R12.CW | v64.14,51.82 82.55,51.82 85.47,48.9 87,48.9 87.88,48.01 R53.CCW | v30.48,33.27 v36.32,33.27
  Bottom 0.178: 30.48,34.67 31.24,34.67 31.62,34.29 R9.1 | 30.48,34.67 28.7,34.67 C14.2 28.57,34.8 28.32,35.05 25.27,35.05 D3.3 | v64.14,51.82 64.14,49.66 IC9.1 64.01,49.53 62.61,49.53 56.64,43.56 49.28,43.56 48.39,42.67 | 30.48,34.67 v30.48,33.27 | v36.32,33.27 38.99,33.27 48.39,42.67 | v65.91,24.26 65.91,25.15 48.39,42.67
+5V  (via drill 0.71)
  Top 0.508: IC6.4 84.45,23.37 84.45,19.05 C22.1 84.71,18.92 v87.25,18.92 | 74.68,2.03 71.88,2.03 71.5,2.41 71.5,4.7 IC1.3 | 74.68,2.03 75.95,2.03 R2.2 | v74.68,2.16 74.68,2.03 | IC2.1 49.4,12.7 49.15,12.7 49.02,12.83 49.02,15.49 C9.1 49.15,15.62 50.55,15.62 | 54.61,14.1 54.61,16.38 C5.+VE 54.48,15.62 50.55,15.62 | 54.61,14.1 54.61,12.83 IC2.8 | IC5.4 17.02,41.15 17.03,41.16 17.03,43.31 17.65,43.94 17.91,43.94 C16.1 18.16,44.07 v19.56,44.07 | v49.53,33.91 49.53,35.69 IC7.4 | v6.48,12.06 6.86,12.45 6.99,12.45 v14.35,19.81 | v48.13,28.45 48.13,25.27 50.55,22.86 50.55,15.62 | v58.93,11.43 56.26,14.1 54.61,14.1
  Bottom 0.508: v87.25,18.92 89.92,16.26 89.92,12.57 79.5,2.16 v74.68,2.16 74.55,2.29 62.99,2.29 58.93,6.35 v58.93,11.43 | C37.1 4.95,12.06 v6.48,12.06 8.38,12.06 IC8.4 | 44.32,32.38 44.45,32.38 | 33.53,32.38 44.32,32.38 | 33.53,32.38 31.75,32.38 R9.2 | v19.56,44.07 21.21,44.07 26.29,38.99 | 26.29,38.99 28.96,36.32 32.38,36.32 33.53,35.18 33.53,32.38 | v14.35,19.81 14.35,27.05 26.29,38.99 | v48.13,28.45 44.32,32.26 44.32,32.38
  Bottom 0.61: 44.45,32.38 44.45,32.45 45.1,33.1 48.72,33.1 49.16,33.54 | 49.16,33.54 v49.53,33.91 | C34.1 47.55,35.15 49.16,33.54
+70V
  Bottom 0.508: IC9.5 70.87,49.66 71.25,50.04 74.3,50.04 C40.1 74.55,50.04 76.07,50.04 80.14,45.97 80.14,38.23 79.38,37.47 C12.+ 79.38,37.21 79.76,36.83 79.76,34.8 83.44,31.11 83.44,25.27 83.57,25.15 | 83.57,25.15 82.04,23.62 82.04,21.72 R5.2 | 83.57,25.15 84.96,25.15 D2.1
  Bottom 0.61: R5.2 81.95,20.35 82.9,19.4 82.9,17.1 81.5,15.7 IC3.2
-4.5V  (via drill 0.71)
  Top 0.508: IC6.11 84.58,28.7 84.58,31.5 C23.1 84.33,31.5 v81.53,31.5 | R8.1 63.88,10.54 63.5,10.16 62.36,10.16 IC4.5 62.23,10.29 v62.23,11.3 62.23,11.43 73.15,22.35 v73.15,23.11 | v60.07,6.73 60.07,5.46 59.05,4.45 C13.-VE | v49.53,28.7 49.53,30.48 IC7.11 | v28.19,22.35 28.19,24.13 27.94,24.38 | 27.94,24.38 20.7,31.62 20.7,31.88 19.05,31.88 C17.1 18.8,32 18.8,33.53 17.27,33.53 17.02,33.78 17.02,35.81 IC5.11 | v17.02,13.46 27.94,24.38
  Bottom 0.508: v62.23,11.3 62.23,8.89 v60.07,6.73 | v81.53,31.5 v73.15,23.11 73.03,23.24 59.69,23.24 53.21,29.72 50.55,29.72 v49.53,28.7 49.53,26.8 C35.1 49.28,26.54 49.28,25.02 49.15,24.89 33.91,24.89 31.37,22.35 29.84,22.35 R10.1 29.59,22.35 v28.19,22.35 | IC8.11 13.72,11.94 17.02,11.94 C38.1 17.02,12.19 v17.02,13.46
-5IN
  Top 0.508: IC4.2 59.82,9.14 59.94,9.02 61.34,9.02 61.34,6.6 61.85,6.1 61.85,2.79 61.21,2.16 55.37,2.16 55.24,2.29 55.24,3.56 54.36,4.45 54.1,4.45 C10.-VE 54.48,4.57 54.48,8.89 IC2.5
CUR_MOD2
  Top 0.178: SW10.COM 93.34,40.51 93.34,44.07 90.42,46.99 90.42,51.44 81.03,60.83 81.03,65.91 J2.CONDUCTOR
CUR_MOD_P3
  Top 0.178: IC6.7 88.39,23.5 90.93,23.5 R38.1 91.06,23.62 96.14,23.62 | 96.14,23.62 96.14,19.56 95.89,19.3 R35.CW 95.76,19.3 95.12,18.67 93.98,18.67 93.34,18.03 R35.W | 96.14,23.62 96.14,23.75 SW3.1 96.14,23.62
CUR_MOD_P4
  Top 0.178: 89.53,28.83 89.53,31.5 R43.2 | 89.53,28.83 89.41,28.7 88.39,28.7 IC6.8 | 89.53,28.83 91.06,27.3 96.14,27.3 SW3.2
GND  (via drill 0.51)  (1 unrouted)
  Bottom 0.406: C40.2 74.3,39.7 67.5,39.7 | 67.5,39.7 60.5,39.7 60.5,39.8 67.5,39.8 67.5,39.7 | 67.5,39.7 IC9.3A
  other vias: 3.9,9.7 3.6,4.2 9.2,17.9 5.9,27 20.6,29.3 26.8,29 23.7,24.1 20.2,26 15.8,17.3 16.3,45.5 26.1,41.1 43.3,33.7 44.5,37.2 49.9,45.3 58.6,50.3 76.4,45.5 47.4,52.3 7.2,49.6 15.6,49.5 30.7,50 23.6,5 90.5,20 98.1,22.3 92.3,29.2 86.3,41.2 74.4,28.8 68.4,5.8 96,6.9 62.1,20.1 51.9,17.8 52.3,13.5 59.3,13.6 66.9,41.1 85.1,26.8 76,23.6 49.4,38 89.4,26.9 35,39.5 10.7,40.5 36.2,19.3 58.4,28 7.2,36.1 1.4,35.4 55.9,57.2 78,56.8 46,21.2 52.7,7.3
  pour Top: 0,0 100,0 100,51 92,51 92,75 0,75
  pour Bottom: 0,0 100,0 100,75 0,75
  pour Bottom: 34,18 34,6 25,6 25,18
INPUT_BUF  (via drill 0.51)  (1 unrouted)
  Top 0.178: 18.29,41.02 18.29,39.12 20.7,39.12 20.7,41.02 IC5.1 20.83,41.15 21.08,41.4 21.97,41.4 22.48,41.91 23.88,41.91 C19.2 24,42.04 24,43.94 R16.1 24,44.07 29.97,44.07 29.97,43.05 32.26,43.05 32.64,42.67 v49.53,42.67 | v73.53,24.77 74.04,24.26 74.04,19.05 75.95,17.14 77.47,17.14 C18.2
  Bottom 0.178: v73.53,24.77 67.31,24.77 49.53,42.55 v49.53,42.67
MOD_SP  (via drill 0.51)  (1 unrouted)
  Top 0.178: v67.82,25.65 64.52,25.65 R11.W | v79.38,30.61 82.55,30.61 82.55,26.54 83.69,25.4 85.72,25.4
  Bottom 0.178: v67.82,25.65 74.42,25.65 v79.38,30.61
N$001  (via drill 0.51)
  Top 0.178: v13.46,25.4 14.73,25.4 14.73,24.38 R52.CCW
  Bottom 0.178: v13.46,25.4 13.46,26.92 13.84,27.3 13.84,33.53 13.34,34.04 13.34,54.74 17.65,59.05 17.65,62.36 19.43,64.14 29.08,64.14 29.46,64.52 31.88,64.52 32.13,64.26 50.42,64.26 52.07,65.91 57.02,65.91 R51.1
N$002  (via drill 0.51)
  Top 0.178: v18.92,17.4 15.37,20.95 14.35,20.95 13.59,21.72 R52.W
  Bottom 0.178: R54.1 19.05,8 19.05,9.53 20.45,10.92 20.45,14.86 20.32,14.99 19.05,14.99 R55.1 18.92,15.11 v18.92,17.4
N$003
  Bottom 0.178: R61.1 11.56,6.1 11.56,9.27 11.68,9.4 13.59,9.4 IC8.13 13.72,9.53 13.84,9.65 16.89,9.65 17.02,9.53 17.02,8 R54.2
N$004
  Top 0.178: R16.2 23.88,45.97 20.57,45.97 19.05,47.5 15.37,47.5 14.99,47.12 R20.1 14.99,46.99 14.99,44.07 C21.1 14.99,43.94 14.48,43.43 14.48,41.15 IC5.6
N$005
  Bottom 0.178: IC8.14 13.59,8.13 13.46,8 13.46,6.1 R61.2 13.46,5.97 17.02,5.97 R63.1
N$006
  Top 0.178: C31.1 65.41,32.51 65.41,36.07 SW1.7
N$007  (via drill 0.51)
  Top 0.178: v18.29,19.81 18.29,21.21 SW6.2
  Bottom 0.178: v18.29,19.81 17.14,18.67 17.14,15.11 R55.2 17.02,14.99 15.75,14.99 15.62,14.86 15.62,12.7 15.49,12.57 12.19,12.57 12.19,10.73 12.95,10.73 13.59,10.79 IC8.12
N$008  (via drill 0.51)
  Top 0.178: v27.18,36.7 v27.18,42.42 | v39.24,59.05 41.4,59.05 46.74,64.39 46.74,65.66 46.99,65.91 J4.CONDUCTOR
  Bottom 0.178: v27.18,36.7 26.54,36.07 24.38,36.07 24.38,35.81 23.88,35.81 22.86,34.8 22.86,33.02 21.72,31.88 21.72,7.87 20.32,6.48 19.43,6.48 19.05,6.1 R63.2 | v27.18,42.42 35.43,50.67 35.43,55.24 v39.24,59.05
N$009
  Top 0.178: R26.CW 52.7,45.85 51.05,45.85 50.93,45.97 50.93,46.86 49.4,48.39 47.88,48.39 R25.CW 47.75,48.51 23.88,48.51 22.35,46.99 20.07,46.99 19.05,48.01 13.84,48.01 13.84,44.07 13.08,44.07 C21.2 | C21.2 13.08,43.94 13.08,41.15 IC5.7 | R24.CW 4.7,37.34 3.05,37.34 2.92,37.47 2.92,43.05 3.05,43.18 4.7,43.18 R22.CW 4.83,43.31 5.21,43.69 6.48,43.69 6.86,44.07 | 6.86,44.07 7.24,44.45 R22.W 6.86,44.07 | 6.86,44.07 12.95,44.07 C21.2
N$010
  Top 0.508: +5.1~+12V.TP 96.39,3.56 92.84,3.56 92.2,4.19 91.06,4.19 91.06,3.65 F1.1
N$011
  Top 0.178: R17.2 82.55,19.05 82.55,20.83 83.19,21.46 83.19,23.37 IC6.3
N$012
  Top 0.178: R27.2 10.92,36.96 10.54,37.34 9.4,37.34 8.89,37.85 8,37.85 7.37,38.48 R24.W
N$13
  Bottom 0.178: R1.2 44.45,17.91 44.07,17.53 43.18,17.53 43.18,17.4 42.42,16.64 40.51,16.64 40.51,15.49 U1.P$1
N$014
  Top 0.178: C25.1 11.05,32 11.05,34.92 R27.1 11.05,35.05 11.43,35.43 12.57,35.43 12.57,37.34 14.35,37.34 14.35,35.94 IC5.9 14.48,35.81 14.48,33.91 14.99,33.4 14.99,32 R34.2
N$015  (via drill 0.51)
  Top 0.178: R39.2 13.08,32 v13.08,33.15 13.08,35.81 IC5.8 | 7.37,31.75 7.37,32.38 R37.W 7.37,31.75 | 7.37,31.75 7.37,30.61 7.87,30.1 v9.65,30.1 10.92,30.1 C25.2 | 7.37,31.75 5.33,31.75 4.83,31.24 R37.CW
  Bottom 0.178: v13.08,33.15 12.7,33.15 v9.65,30.1
N$016
  Top 0.178: C29.1 70.48,32.51 70.48,36.07 SW1.9
N$17
  Bottom 0.178: C3.1 46.48,16 46.48,17.91 R1.1
N$018
  Top 0.178: C30.1 67.94,32.51 67.94,36.07 SW1.8
N$19
  Bottom 0.178: 44.58,13.59 44.58,13.97 R4.2 44.58,13.59 | 44.58,13.59 44.58,11.56 R3.1 | 44.58,13.59 40.64,13.59 40.51,13.72 U1.P$2
N$020
  Top 0.178: C32.1 62.87,32.51 62.87,36.07 SW1.6
N$021
  Top 0.178: C28.2 73.03,30.61 70.61,30.61 C29.2 70.48,30.61 68.07,30.61 C30.2 67.94,30.61 65.53,30.61 C31.2 65.41,30.61 62.99,30.61 C32.2 62.87,30.61 57.91,30.61 57.53,30.99 57.02,30.99 57.02,36.07 56.13,36.96 | 56.52,40.77 57.4,40.77 R40.2 | 56.52,40.77 55.63,40.77 C26.2 | 56.52,40.77 56.52,37.34 56.13,36.96 | 56.13,36.96 55.37,36.2 53.47,36.2 53.34,36.07 53.34,35.81 IC7.1
N$22
  Bottom 0.508: U1.P$4 40.39,10.29 37.97,10.29 37.85,10.16 37.85,7.75 38.35,7.24 38.35,5.97 39.24,5.08 39.5,5.08 D1.A- 39.75,4.83 39.75,2.67 45.47,2.67 51.69,8.89 55.88,8.89 L1.2
N$023
  Top 0.178: R29.2 53.59,40.77 53.59,43.69 55.24,45.34 55.24,47.12 R26.W
N$024  (via drill 0.51)
  Top 0.178: IC5.12 18.29,35.94 18.29,37.85 18.41,37.97 23.88,37.97 C20.2 24,37.85 25.53,37.85 25.65,37.72 25.65,36.83 27.43,35.05 v27.43,31.37
  Bottom 0.178: R13.2 33.02,28.32 30.73,28.32 R14.1 30.61,28.32 30.23,28.7 30.23,29.59 28.45,31.37 v27.43,31.37
N$025  (via drill 0.51)
  Top 0.178: v40.13,26.04 43.56,22.61 v49.53,22.61 | v52.45,22.61 70.74,22.61 71.88,23.75 71.88,25.53 R12.W
  Bottom 0.178: v40.13,26.04 33.53,26.04 33.15,26.42 R13.1 | v49.53,22.61 v52.45,22.61
N$026  (via drill 0.51)
  Top 0.178: IC7.2 52.07,35.81 52.58,36.32 52.58,38.48 52.83,38.73 53.47,38.73 R29.1 53.59,38.86 55.5,38.86 C26.1 55.63,38.73 v55.63,37.59 | SW1.1 73.03,44.83 70.61,44.83 SW1.2 70.48,44.83 68.07,44.83 SW1.3 67.94,44.83 65.53,44.83 SW1.4 65.41,44.83 62.99,44.83 SW1.5 62.87,44.7 61.34,44.7 60.33,43.69 v60.33,42.29
  Bottom 0.178: v55.63,37.59 v60.33,42.29
N$027
  Top 0.178: C28.1 73.03,32.51 73.03,36.07 SW1.10
N$028
  Top 0.178: SW10.1 95.63,38.73 95.63,36.7 93.34,34.42 93.34,32.51 R45.W
N$029  (via drill 0.51)
  Top 0.178: v43.69,27.94 43.69,26.92 43.94,26.67 R47.1 | v40.13,31.24 41.4,31.24 C33.2 41.53,31.24 43.94,31.24 R46.1 44.07,31.11 45.09,31.11 45.59,30.61 IC7.8 45.72,30.61 45.72,32.51 45.85,32.64 49.53,32.64 50.67,33.78 55.12,33.78 55.75,34.42 SW4.1
  Bottom 0.178: v43.69,27.94 43.43,27.94 v40.13,31.24
N$030
  Top 0.178: R33.2 41.53,35.56 43.31,35.56 45.09,33.78 48.01,33.78 48.13,33.91 48.13,35.69 IC7.5
N$031
  Top 0.178: R18.1 23.88,31.11 22.35,31.11 19.56,33.91 19.56,35.81 IC5.13
N$032
  Top 0.178: R28.1 16.89,32 16.51,32.38 16.51,33.27 15.88,33.91 15.88,35.69 15.75,35.81 IC5.10
N$033  (via drill 0.71)
  Top 0.508: v48.64,7.49 49.66,7.49 51.18,5.97 51.18,2.79 52.45,1.52 54.99,1.52 54.99,1.4 69.09,1.4 v69.09,3.3
  Bottom 0.508: 46.35,9.78 46.35,11.43 R3.2 | 46.35,9.78 43.81,7.24 43.81,5.46 43.43,5.08 D1.K+ | D2.3 86.11,22.86 86.11,18.29 86.61,17.78 86.61,15.24 85.85,14.48 C8.+ 85.6,14.35 84.45,13.21 80.9,13.21 IC3.3 80.64,12.95 80.64,11.56 72.39,3.3 v69.09,3.3 | 46.35,9.78 v48.64,7.49
N$034
  Bottom 0.178: R6.2 79.76,24.89 80.01,24.64 80.01,21.72 R5.1 80.14,21.59 80.14,20.19 80.26,20.07 80.26,18.8 80.77,18.29 IC3.1
N$035  (via drill 0.51)
  Top 0.178: v39.88,29.21 38.61,29.21 R44.1 | v45.59,27.05 47.24,28.7 47.24,28.91 48.23,29.91 48.23,29.97 48.13,30.48 IC7.10
  Bottom 0.178: v39.88,29.21 41.15,29.21 43.31,27.05 v45.59,27.05
N$036  (via drill 0.51)
  Top 0.178: v1.78,15.88 1.78,15.37 v6.35,10.79
  Bottom 0.178: 6.48,10.67 6.1,10.29 6.1,9.02 R50.1 | 6.48,10.67 8.38,10.67 IC8.3 | v1.78,15.88 2.92,15.88 R56.1 | 6.48,10.67 v6.35,10.79
N$037
  Top 0.178: R48.2 51.44,26.67 51.44,28.07 50.8,28.7 50.8,30.48 IC7.12
N$038
  Top 0.178: R49.2 55.5,26.67 53.59,26.67 C36.2 53.47,26.67 53.47,30.86 | 53.47,30.86 55.75,30.86 SW4.2 | 53.47,30.86 53.21,30.61 IC7.14 53.47,30.86
N$039
  Top 0.178: R20.2 12.95,46.99 6.99,46.99 6.35,46.35 5.46,46.35 4.83,45.72 R22.CCW
N$040  (via drill 0.51)
  Top 0.178: v43.05,38.86 44.45,38.86 C24.1 | v44.83,45.47 44.83,46.74 45.21,47.12 R25.W
  Bottom 0.178: v43.05,38.86 43.05,43.69 v44.83,45.47
N$041
  Top 0.178: IC2.2 49.4,11.56 42.93,11.56 42.55,11.94 C7.+VE
N$042
  Top 0.178: IC2.4 49.4,8.89 47.37,8.89 44.58,6.1 42.55,6.1 C7.-VE
N$043  (via drill 0.51)
  Top 0.178: v3.43,24.26 4.7,24.26 R64.CW
  Bottom 0.178: 6.35,15.88 8.38,15.88 IC8.7 | 6.35,15.88 4.95,15.88 R56.2 | 3.43,19.68 5.71,19.68 6.35,19.05 6.35,15.88 | 3.43,19.68 3.17,19.68 3.05,19.56 3.05,18.03 C39.2 | 3.43,19.68 v3.43,24.26
N$044
  Bottom 0.178: IC8.1 8.38,8.13 8.38,7.11 6.1,7.11 R50.2 5.97,7.11 4.45,7.11 1.4,10.16 1.4,13.46 1.65,13.72 2.67,13.72 2.92,13.97 R58.1
N$045
  Bottom 0.178: 5.21,14.35 5.33,14.48 8.38,14.48 IC8.6 | 5.21,14.35 4.95,14.1 R58.2 5.21,14.35 | 5.21,14.35 4.06,14.35 4.06,17.02 4.7,17.02 4.83,17.14 4.83,17.91 C39.1
N$046
  Bottom 0.178: R59.2 71.88,55.37 69.47,55.37 R62.1 69.34,55.24 67.82,55.24 67.56,54.99 67.56,53.72 67.44,53.59 66.04,53.59 65.91,53.47 R60.1 65.91,53.34 65.91,49.66 IC9.2
N$047  (via drill 0.51)
  Top 0.178: v65.02,56.77 65.02,55.88 v67.94,52.96
  Bottom 0.178: R66.1 63.12,61.09 64.9,61.09 R65.1 65.02,60.96 v65.02,56.77 | 69.34,52.96 69.34,49.78 69.22,49.66 IC9.4 | 69.34,52.96 69.34,53.34 R62.2 69.34,52.96 | 69.34,52.96 v67.94,52.96
N$048
  Bottom 0.178: R59.1 72.01,53.34 75.06,53.34 80.39,48.01 82.8,48.01 R53.W
N$049  (via drill 0.51)
  Top 0.178: v56.77,53.47 55.37,53.47 R57.W
  Bottom 0.178: v56.77,53.47 58.55,55.24 65.79,55.24 R60.2
N$050
  Top 0.178: R36.1 38.61,40.77 41.4,40.77 C27.1 41.53,40.77 41.78,41.02 41.78,42.04 42.04,42.29 47.88,42.29 48.64,41.53 48.64,38.99 48.51,38.86 47.12,38.86 R30.2 46.99,38.73 46.99,35.81 IC7.6
N$051
  Top 0.178: R41.2 38.48,35.69 38.48,38.73 R36.2 38.61,38.86 41.4,38.86 C27.2 41.53,38.73 41.53,37.34 42.29,37.34 43.81,35.81 45.59,35.81 IC7.7
N$052
  Top 0.178: C24.2 44.58,40.77 46.99,40.77 R30.1
N$053  (via drill 0.51)
  Top 0.178: v48.64,23.5 47.5,24.64 44.07,24.64 R47.2 | v53.47,23.5 53.47,24.64 C36.1 53.59,24.77 55.5,24.77 R49.1 55.63,24.77 v56.9,24.77 | v52.07,28.83 52.07,30.48 IC7.13
  Bottom 0.178: v48.64,23.5 v53.47,23.5 | v52.07,28.83 52.83,28.83 v56.9,24.77
N$054
  Top 0.178: R42.2 87,31.5 86.74,31.5 86.36,31.11 86.36,29.21 85.85,28.7 IC6.10
N$055
  Top 0.178: R64.W 5.97,21.84 4.06,21.84 2.54,23.37 2.54,46.99 6.22,50.67 6.22,52.96 SW7.NC
N$056
  Top 0.178: R32.1 51.44,38.73 51.05,38.35 51.05,36.07 50.8,35.81 IC7.3
N$057
  Top 0.178: IC4.3 59.69,8.26 57.28,8.26 57.02,8.51 C11.2
N$058  (1 unrouted)
N$059
  Top 0.178: J3.CONDUCTOR 9.02,65.91 9.02,60.96 14.73,55.24 14.73,53.98 15.62,53.09 SW7.NO
N$060
  Top 0.178: IC4.4 62.36,8.26 63.63,8.26 63.88,8.51 R8.2 64.01,8.64 66.93,8.64 R7.1
N$061
  Top 0.178: IC7.9 46.86,30.48 46.86,29.73 46.35,29.22 46.35,29.21 44.07,29.21 R46.2 43.94,29.34 41.53,29.34 C33.1 41.4,29.34 41.02,28.96 41.02,27.94 40.89,27.81 34.42,27.81 32.26,29.97 28.96,29.97 SW2.COM 28.83,30.1 28.83,36.45 SW9.COM 28.83,36.58 28.83,42.93 SW8.COM
N$062
  Top 0.178: IC6.14 80.77,28.57 81.92,28.57 IC6.13
N$063
  Top 0.178: 78.61,33.27 78.23,33.27 R21.CW 78.61,33.27 | 78.61,33.27 78.99,33.66 80.01,33.66 80.77,34.42 R21.W | 80.52,21.34 80.52,23.24 80.64,23.37 IC6.1 | 80.52,21.34 80.52,19.05 R23.1 | 78.61,33.27 78.61,29.34 79.5,28.45 79.5,27.18 80.26,26.42 81.53,26.42 82.55,25.4 82.55,21.46 82.42,21.34 80.52,21.34
N$085
  Top 0.178: R34.1 14.99,30.1 14.22,30.1 13.97,30.35 13.97,30.86 9.53,30.86 9.02,31.37 9.02,33.91 8.51,34.42 4.83,34.42 4.83,33.78 R37.CCW
N$091  (via drill 0.51)  (1 unrouted)
  Top 0.178: v21.97,45.21 19.94,43.18 19.68,43.18 19.56,43.05 19.56,41.15 IC5.2 | v21.97,47.75 21.97,60.33 26.04,64.39 26.04,65.91 J1.CONDUCTOR
  Bottom 0.178: v21.97,45.21 v21.97,47.75
N$093  (via drill 0.51)
  Top 0.178: R12.CCW 69.34,26.92 61.98,26.92 R11.CCW 61.85,26.8 60.07,26.8 v56.9,23.62
  Bottom 0.178: D4.1 26.16,26.42 28.57,26.42 C15.1 28.7,26.42 29.21,25.91 29.21,24.64 29.46,24.38 | 29.46,24.38 29.59,24.26 R10.2 29.46,24.38 | 29.46,24.38 29.08,24 28.19,24 27.3,23.11 27.3,21.97 28.32,20.95 31.97,20.95 35.27,24.26 56.26,24.26 v56.9,23.62
N$097
  Top 0.178: C18.1 77.47,19.05 77.47,21.97 R15.1
N$098
  Top 0.178: 77.47,25.65 77.47,26.04 R19.1 77.47,25.65 | 77.47,25.65 77.47,24 R15.2 | 77.47,25.65 81.66,25.65 81.92,25.4 81.92,23.5 IC6.2
N$100
  Top 0.178: R23.2 80.52,17.02 80.9,16.64 80.9,15.75 81.15,15.49 85.47,15.49 86.23,16.26 86.23,16.89 87.5,16.89 R31.1 87.63,17.02 88.14,17.02 88.14,19.3 87.12,20.32 87.12,23.37 IC6.6
N$101
  Top 0.178: R38.2 90.93,25.53 88.27,25.53 87.12,26.67 87.12,28.57 IC6.9 87.12,28.7 87.12,29.97 88.01,29.97 88.01,33.02 89.03,33.02 89.41,33.4 R43.1
N$102  (via drill 0.51)
  Top 0.178: v56.26,44.32 59.05,41.53 59.05,38.86 57.53,38.86 R40.1 | v44.83,44.32 31.62,44.32 31.24,44.7 SW8.2
  Bottom 0.178: v44.83,44.32 v56.26,44.32
N$103
  Top 0.178: R41.1 38.48,33.78 36.96,33.78 32.77,37.97 31.5,37.97 31.24,38.23 SW9.2
N$104  (via drill 0.51)
  Top 0.178: v22.61,28.32 22.35,28.07 14.1,28.07 13.46,28.7 13.46,29.59 13.08,29.97 R39.1 | v29.59,31.62 30.99,31.62 31.11,31.75 SW2.2
  Bottom 0.178: v22.61,28.32 22.61,28.57 25.27,31.24 25.27,33.91 29.72,33.91 29.72,31.62 v29.59,31.62
N$105
  Top 0.178: R19.2 77.47,28.07 77.47,31.24 76.45,32.26 76.45,35.56 76.58,35.69 78.11,35.69 R21.CCW
N$106
  Top 0.178: R31.2 89.53,16.89 91.19,16.89 91.95,16.13 95.12,16.13 95.76,16.76 R35.CCW
N$107
  Top 0.178: SW3.COM 93.85,25.53 97.28,25.53 97.92,26.16 97.92,33.15 97.41,33.66 95.89,33.66 R45.CW
PID_OUT
  Top 0.178: SW4.COM 58.17,32.77 58.17,36.96 59.44,38.23 59.44,46.1 55.5,50.04 43.43,50.04 42.42,49.02 38.86,49.02 37.21,50.67 37.21,52.96 SW5.NC
PIEZO_CTRL1
  Top 0.178: R57.CCW 52.7,54.74 44.7,54.74 42.55,56.9 34.16,56.9 32.51,55.24 32.51,53.09 SW5.C
SCAN_O  (via drill 0.51)  (1 unrouted)
  Top 0.178: v18.41,28.83 18.41,28.57 14.99,28.57 14.86,28.7 v14.86,28.83
  Bottom 0.178: 13.72,13.34 14.35,13.97 14.99,13.97 14.99,15.11 14.35,15.11 13.72,15.75 IC8.8 13.72,15.88 13.72,17.91 18.41,22.61 v18.41,28.83 | v14.86,28.83 14.86,40.64 19.18,44.96 21.08,44.96 21.59,44.45 22.48,44.45 27.69,49.66 27.69,52.96 SW5.NO | 10.92,52.96 10.92,50.67 8.89,48.64 8.89,29.72 10.41,28.19 10.41,15.88 11.68,14.61 13.59,14.61 IC8.9
SETPOINT  (via drill 0.51)
  Top 0.178: R18.2 23.88,33.02 v21.72,33.02 20.83,33.91 20.83,35.81 IC5.14 20.83,35.94 v21.84,35.94 | v15.75,39.24 15.75,41.02 IC5.5 | v6.6,13.34 7.87,14.61 7.87,23.5 7.37,24 7.37,24.26 R64.CCW 7.37,24.38 8.76,24.38 11.05,26.67 v15.24,26.67
  Bottom 0.178: v15.75,39.24 18.54,39.24 v21.84,35.94 | v6.6,13.34 8.38,13.34 IC8.5 8.51,13.21 10.41,13.21 10.41,9.53 8.51,9.53 IC8.2 | v21.72,33.02 21.46,33.02 15.24,26.8 v15.24,26.67
VIN  (via drill 0.71)
  Top 0.508: C2.2 81.03,3.94 84.33,3.94 84.58,4.19 84.58,4.17 84.65,4.1 | 84.71,4.45 F1.2 84.65,4.1 | v40.39,7.37 40.26,7.37 40.13,7.49 40.13,15.62 v42.29,17.78 | v68.45,8.51 70.61,8.51 71.25,9.14 IC1.1 71.5,9.4 72.39,10.29 72.39,11.56 72.52,11.68 82.22,11.68 82.9,11 84.45,11 C1.+ 84.65,4.1
  Bottom 0.508: C6.2 40.89,18.03 | v40.39,7.37 40.39,8.51 U1.P$5 | C6.2 41.02,17.78 v42.29,17.78 42.55,18.03 42.55,18.67 43.43,19.56 48.13,19.56 48.64,20.07 55.88,20.07 L1.1 55.88,19.81 58.93,19.81 63.25,15.49 63.25,8.89 63.88,8.26 68.33,8.26 68.45,8.38 v68.45,8.51 | C4.+ 39.35,21.55 41,19.9 41,18.05 C6.2
VPIEZO
  Bottom 0.178: R51.2 59.05,65.91 59.05,64.39 59.31,64.14 60.33,64.14 61.47,62.99 62.99,62.99 R66.2 | 63.5,62.99 63.12,62.99 R66.2 | 63.5,62.99 64.9,62.99 R65.2 | 63.5,62.99 63.5,65.53 63.88,65.91 J5.CONDUCTOR | R66.2 63.5,62.99

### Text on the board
Top: Pandora Driver | Rev: A
Graphics: Mov SW10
